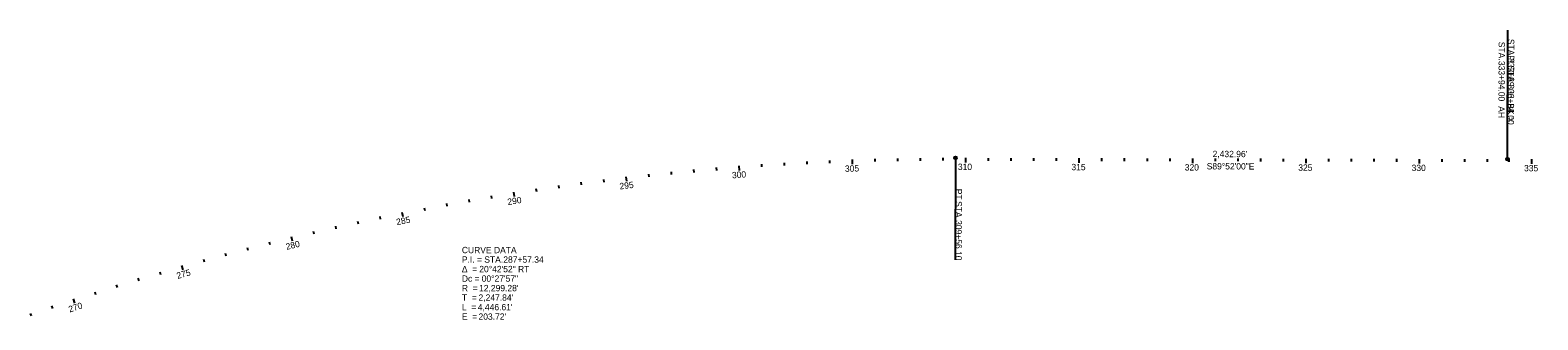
# Model space of a CAD drawing. Extents: x 117326 to 225548, y 573011 to 581051.
# Drawn here: x 144347 to 150993, y 576812 to 578092 of the extents above; entities that cross this region are included whole.
import ezdxf

# ---------------------------------------------------------------- set-up
doc = ezdxf.new("R2010")
doc.units = 0
for name, color, linetype in [('_CIVIL_CONSTRUCTION', 7, 'Continuous'), ('GE_P_Alignment', 7, 'Continuous'), ('GE_P_Alignment_100_Bearings', 7, 'Continuous'), ('GE_P_Alignment_100_Cardinal_Points', 7, 'Continuous'), ('GE_P_Alignment_100_Curve_Data', 7, 'Continuous')]:
    doc.layers.add(name, color=color, linetype=linetype)

msp = doc.modelspace()

# ---------------------------------------------------------------- linework, layer by layer
at = {"layer": 'GE_P_Alignment'}
for p, q in [((150859.4, 577521.5), (150860.7, 578091.5)), ((150859.4, 577521.5), (150860.5, 577971.5)), ((148426.4, 577527.2), (148425.4, 577077.2))]:
    msp.add_line(p, q, dxfattribs=at)
for centre in [(148426.4, 577527.2), (150859.4, 577521.5), (150859.4, 577521.5)]:
    msp.add_circle(centre, 6, dxfattribs=at)
at = {"layer": 'GE_P_Alignment_100_Curve_Data'}
for p, q in [((147970.4, 577519.8), (147971.1, 577499.8)), ((148070.3, 577522.9), (148070.7, 577510.9)), ((148170.3, 577525.1), (148170.5, 577513.1)), ((148270.3, 577526.6), (148270.4, 577514.6)), ((148370.3, 577527.2), (148370.3, 577515.2)), ((148470.3, 577527.1), (148470.3, 577507.1)), ((148570.3, 577526.9), (148570.3, 577514.9)), ((148670.3, 577526.6), (148670.3, 577514.6)), ((148770.3, 577526.4), (148770.3, 577514.4)), ((148870.3, 577526.2), (148870.3, 577514.2)), ((148970.3, 577525.9), (148970.2, 577505.9)), ((149070.3, 577525.7), (149070.3, 577513.7)), ((149170.3, 577525.5), (149170.3, 577513.5)), ((149270.3, 577525.2), (149270.3, 577513.2)), ((149370.3, 577525), (149370.3, 577513)), ((149470.3, 577524.8), (149470.2, 577504.8)), ((149570.3, 577524.5), (149570.3, 577512.5)), ((149670.3, 577524.3), (149670.3, 577512.3)), ((149770.3, 577524.1), (149770.3, 577512.1)), ((149870.3, 577523.8), (149870.3, 577511.8)), ((149970.3, 577523.6), (149970.2, 577503.6)), ((150070.3, 577523.4), (150070.3, 577511.4)), ((150170.3, 577523.1), (150170.3, 577511.1)), ((150270.3, 577522.9), (150270.3, 577510.9)), ((150370.3, 577522.7), (150370.3, 577510.7)), ((150470.3, 577522.4), (150470.2, 577502.4)), ((150570.3, 577522.2), (150570.3, 577510.2)), ((150670.3, 577522), (150670.3, 577510)), ((150770.3, 577521.7), (150770.3, 577509.7)), ((150865.4, 577521.5), (150865.3, 577509.5)), ((150965.4, 577521.3), (150965.3, 577501.3)), ((147072.9, 577455.7), (147074.2, 577443.7)), ((147172.3, 577466), (147173.5, 577454.1)), ((147271.9, 577475.6), (147273, 577463.6)), ((147371.5, 577484.3), (147372.5, 577472.4)), ((147471.2, 577492.3), (147472.7, 577472.3)), ((147570.9, 577499.4), (147571.7, 577487.4)), ((147670.7, 577505.7), (147671.4, 577493.7)), ((147770.6, 577511.2), (147771.2, 577499.2)), ((147870.5, 577515.9), (147871, 577503.9)), ((146577, 577391.7), (146578.8, 577379.8)), ((146676, 577406.1), (146677.7, 577394.2)), ((146775, 577419.7), (146776.6, 577407.8)), ((146874.2, 577432.5), (146875.7, 577420.6)), ((146973.5, 577444.5), (146975.8, 577424.6)), ((146182.5, 577326.1), (146184.6, 577314.3)), ((146280.9, 577343.7), (146283, 577331.9)), ((146379.5, 577360.5), (146381.4, 577348.7)), ((146478.2, 577376.5), (146481.3, 577356.7)), ((145888, 577268.4), (145890.5, 577256.7)), ((145986, 577288.4), (145989.9, 577268.8)), ((146084.2, 577307.7), (146086.4, 577295.9)), ((145595.1, 577203.6), (145597.9, 577192)), ((145692.6, 577226), (145695.2, 577214.3)), ((145790.2, 577247.6), (145792.8, 577235.9)), ((145303.9, 577131.7), (145306.9, 577120.1)), ((145400.8, 577156.5), (145403.7, 577144.9)), ((145497.9, 577180.5), (145502.6, 577161)), ((145014.5, 577052.7), (145020, 577033.5)), ((145110.7, 577079.8), (145113.9, 577068.3)), ((145207.2, 577106.2), (145210.3, 577094.6)), ((144822.7, 576996.2), (144826.1, 576984.7)), ((144918.5, 577024.8), (144921.9, 577013.3)), ((144631.8, 576936.5), (144635.5, 576925)), ((144727.1, 576966.7), (144730.7, 576955.2)), ((144441.9, 576873.7), (144445.8, 576862.3)), ((144536.7, 576905.5), (144543, 576886.5)), ((144347.3, 576841.1), (144351.3, 576829.8))]:
    msp.add_line(p, q, dxfattribs=at)

# ---------------------------------------------------------------- texts
at = {"layer": '_CIVIL_CONSTRUCTION'}
msp.add_text('S89°52\'00"E', height=28, rotation=359.86678, dxfattribs=at).set_placement((149533.4, 577476.6))
at = {"layer": 'GE_P_Alignment'}
for s, rotation, p in [('STA. ', 269.86678, (150861, 578052.7)), ('STA. ', 269.86678, (150820.1, 578040.1)), ('333+94.00', 269.86678, (150819.9, 577955.5)), ('333+89.06', 269.86678, (150860.8, 577968.1)), (' STA. ', 269.85657, (150860.8, 577946.6)), ('PI', 269.85657, (150860.9, 577980.5)), ('333+94.00', 269.85657, (150860.6, 577852)), (' AH', 269.86678, (150819.4, 577766)), (' BK =', 269.86678, (150860.4, 577778.6)), ('PT', 269.86678, (148426.5, 577391.2)), (' STA. ', 269.86678, (148426.4, 577347.1)), ('309+56.10', 269.86678, (148426.2, 577252.6))]:
    msp.add_text(s, height=28, rotation=rotation, dxfattribs=at).set_placement(p)
at = {"layer": 'GE_P_Alignment_100_Bearings'}
for s, p in [('CURVE DATA', (146250.3, 577106.7)), ('P.I. = STA. ', (146250.3, 577064.7)), ('287+57.34', (146433, 577064.7)), ('Δ  = ', (146250.3, 577022.7)), ('Dc = ', (146250.3, 576980.7)), ('20°42\'52" RT', (146327.1, 577022.7)), ('00°27\'57"', (146337.7, 576980.7)), ('T  = ', (146250.3, 576896.7)), ('R  = ', (146250.3, 576938.7)), ("2,247.84'", (146323.7, 576896.7)), ("12,299.28'", (146326.1, 576938.7)), ('L  = ', (146250.3, 576854.7)), ("4,446.61'", (146320.7, 576854.7)), ('E  = ', (146250.3, 576812.7)), ("203.72'", (146323.7, 576812.7))]:
    msp.add_text(s, height=28, dxfattribs=at).set_placement(p)
at = {"layer": 'GE_P_Alignment_100_Cardinal_Points'}
msp.add_text("2,432.96'", height=28, rotation=359.86678, dxfattribs=at).set_placement((149559.4, 577530.8))
at = {"layer": 'GE_P_Alignment_100_Curve_Data'}
for s, rotation, p in [('300', 4.32074, (147441.8, 577436.9)), ('305', 1.99151, (147939.2, 577465.7)), ('310', 359.86678, (148436.7, 577474.2)), ('315', 359.86678, (148937.1, 577473)), ('320', 359.86678, (149436.7, 577471.8)), ('325', 359.86678, (149937.1, 577470.7)), ('330', 359.86678, (150436.7, 577469.5)), ('335', 359.85657, (150932.2, 577468.4)), ('295', 6.64998, (146946.8, 577388)), ('290', 8.97921, (146453.4, 577318.9)), ('285', 11.30844, (145964, 577230)), ('280', 13.63767, (145477.8, 577121.1)), ('275', 15.96691, (144997.3, 576992.7)), ('270', 18.29614, (144521.6, 576844.6))]:
    msp.add_text(s, height=28, rotation=rotation, dxfattribs=at).set_placement(p)

doc.saveas('drawing.dxf')
